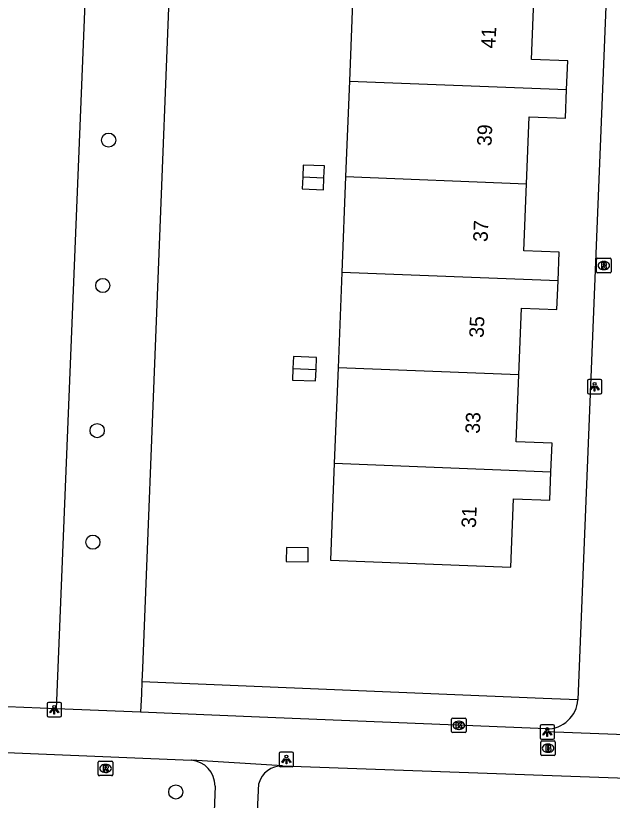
# Model space of a CAD drawing. Extents: x 160787 to 161428, y 386828 to 387483.
# Drawn here: x 161138.7 to 161179.8, y 387067.7 to 387121.8 of the extents above; entities that cross this region are included whole.
import ezdxf

# ---------------------------------------------------------------- set-up
doc = ezdxf.new("R2010")
doc.units = 0
for name, color, linetype in [('IMGEO_Boom', 7, 'Continuous'), ('IMGEO_Brandkraan', 7, 'Continuous'), ('IMGEO_Groenvoorziening', 7, 'Continuous'), ('IMGEO_Haag', 7, 'Continuous'), ('IMGEO_Kolk', 7, 'Continuous'), ('IMGEO_Lichtpunt', 7, 'Continuous'), ('IMGEO_Pand', 7, 'Continuous'), ('IMGEO_Pand_nummerreeks', 7, 'Continuous'), ('IMGEO_Rioolput', 7, 'Continuous'), ('IMGEO_Voetpad_open', 7, 'Continuous')]:
    doc.layers.add(name, color=color, linetype=linetype)

msp = doc.modelspace()

# ---------------------------------------------------------------- linework, layer by layer
at = {"layer": 'IMGEO_Boom'}
for centre in [(161145.069, 387113.242), (161144.667, 387103.214), (161144.278, 387093.199), (161143.985, 387085.507), (161149.703, 387068.275)]:
    msp.add_circle(centre, 0.489, dxfattribs=at)
at = {"layer": 'IMGEO_Brandkraan'}
for p, q in [((161174.885, 387070.866), (161174.885, 387071.718)), ((161174.96, 387071.792), (161175.812, 387071.792)), ((161175.373, 387071.572), (161175.398, 387071.572)), ((161175.886, 387071.718), (161175.886, 387070.866)), ((161175.396, 387071.012), (161175.371, 387071.012)), ((161175.812, 387070.792), (161174.96, 387070.792))]:
    msp.add_line(p, q, dxfattribs=at)
for points in [[(161174.885, 387070.866), (161174.885, 387071.718)], [(161174.96, 387071.792), (161175.812, 387071.792)], [(161175.233, 387071.492), (161175.233, 387071.092), (161175.446, 387071.092)], [(161175.464, 387071.492), (161175.233, 387071.492)], [(161175.886, 387071.718), (161175.886, 387070.866)], [(161175.412, 387071.411), (161175.358, 387071.411), (161175.358, 387071.335)], [(161175.358, 387071.335), (161175.411, 387071.335)], [(161175.42, 387071.259), (161175.358, 387071.259), (161175.358, 387071.178)], [(161175.358, 387071.178), (161175.42, 387071.178)], [(161175.812, 387070.792), (161174.96, 387070.792)]]:
    msp.add_lwpolyline(points, dxfattribs=at)
for centre, radius, start, end in [((161174.962, 387071.716), 0.0765, 91.552, 178.448), ((161174.962, 387071.716), 0.0765, 91.552, 178.448), ((161175.468, 387071.347), 0.145, 59.4692, 91.5367), ((161175.493, 387071.394), 0.0922, 285.5137, 58.1501), ((161175.81, 387071.716), 0.0765, 1.552, 88.448), ((161175.81, 387071.716), 0.0765, 1.552, 88.448), ((161175.413, 387071.373), 0.0379, 267.8285, 90.9355), ((161175.421, 387071.218), 0.0404, 269.8759, 90.5077), ((161175.452, 387071.343), 0.251, 268.6676, 293.5347), ((161175.498, 387071.202), 0.105, 301.3115, 78.989), ((161174.962, 387070.868), 0.0765, 181.552, 268.448), ((161174.962, 387070.868), 0.0765, 181.552, 268.448), ((161175.81, 387070.868), 0.0765, 271.552, 358.448), ((161175.81, 387070.868), 0.0765, 271.552, 358.448)]:
    msp.add_arc(centre, radius, start, end, dxfattribs=at)
for centre, major_axis, ratio, start_param, end_param in [((161175.372, 387071.292), (-0.387, 0.002), 0.722429, 4.712389, 7.853982), ((161175.397, 387071.292), (-0.39, 0.002), 0.717154, 1.570796, 4.712389)]:
    msp.add_ellipse(centre, major_axis=major_axis, ratio=ratio, start_param=start_param, end_param=end_param, dxfattribs=at)
at = {"layer": 'IMGEO_Groenvoorziening'}
for points in [[(161141.468, 387074.009), (161145.662, 387177.089), (161145.68, 387177.521)], [(161151.352, 387177.28), (161147.399, 387076.814), (161147.362, 387075.865)]]:
    msp.add_lwpolyline(points, dxfattribs=at)
at = {"layer": 'IMGEO_Haag'}
for points in [[(161147.362, 387075.865), (161147.329, 387075.034), (161147.279, 387073.767)], [(161177.45, 387074.628), (161175.052, 387074.729), (161147.362, 387075.865)]]:
    msp.add_lwpolyline(points, dxfattribs=at)
at = {"layer": 'IMGEO_Kolk'}
for p, q in [((161168.735, 387072.439), (161168.735, 387073.291)), ((161168.81, 387073.365), (161169.662, 387073.365)), ((161169.223, 387073.145), (161169.248, 387073.145)), ((161169.736, 387073.291), (161169.736, 387072.439)), ((161169.246, 387072.585), (161169.221, 387072.585)), ((161169.662, 387072.365), (161168.81, 387072.365))]:
    msp.add_line(p, q, dxfattribs=at)
for points in [[(161168.735, 387072.439), (161168.735, 387073.291)], [(161168.81, 387073.365), (161169.662, 387073.365)], [(161169.736, 387073.291), (161169.736, 387072.439)], [(161169.056, 387073.065), (161169.179, 387073.065), (161169.179, 387072.914), (161169.309, 387073.065), (161169.473, 387073.065), (161169.327, 387072.914), (161169.48, 387072.665), (161169.328, 387072.665), (161169.243, 387072.829), (161169.179, 387072.762), (161169.179, 387072.665), (161169.056, 387072.665), (161169.056, 387073.065)], [(161169.662, 387072.365), (161168.81, 387072.365)]]:
    msp.add_lwpolyline(points, dxfattribs=at)
for centre, start, end in [((161168.812, 387073.289), 91.552, 178.448), ((161168.812, 387073.289), 91.552, 178.448), ((161169.66, 387073.289), 1.552, 88.448), ((161169.66, 387073.289), 1.552, 88.448), ((161168.812, 387072.441), 181.552, 268.448), ((161168.812, 387072.441), 181.552, 268.448), ((161169.66, 387072.441), 271.552, 358.448), ((161169.66, 387072.441), 271.552, 358.448)]:
    msp.add_arc(centre, 0.0765, start, end, dxfattribs=at)
for centre, major_axis, ratio, start_param, end_param in [((161169.222, 387072.865), (-0.387, 0.002), 0.722429, 4.712389, 7.853982), ((161169.247, 387072.865), (-0.39, 0.002), 0.717154, 1.570796, 4.712389)]:
    msp.add_ellipse(centre, major_axis=major_axis, ratio=ratio, start_param=start_param, end_param=end_param, dxfattribs=at)
at = {"layer": 'IMGEO_Lichtpunt'}
for p, q in [((161178.1, 387096.63), (161178.1, 387095.823)), ((161178.1, 387096.63), (161178.1, 387095.823)), ((161179.002, 387096.725), (161178.194, 387096.725)), ((161179.002, 387096.725), (161178.194, 387096.725)), ((161179.096, 387095.823), (161179.096, 387096.63)), ((161179.096, 387095.823), (161179.096, 387096.63)), ((161178.194, 387095.729), (161179.002, 387095.729)), ((161178.194, 387095.729), (161179.002, 387095.729)), ((161140.823, 387074.347), (161140.823, 387073.54)), ((161140.823, 387074.347), (161140.823, 387073.54)), ((161141.725, 387074.442), (161140.917, 387074.442)), ((161141.725, 387074.442), (161140.917, 387074.442)), ((161141.819, 387073.54), (161141.819, 387074.347)), ((161141.819, 387073.54), (161141.819, 387074.347)), ((161140.917, 387073.446), (161141.725, 387073.446)), ((161140.917, 387073.446), (161141.725, 387073.446)), ((161174.833, 387072.812), (161174.833, 387072.005)), ((161174.833, 387072.812), (161174.833, 387072.005)), ((161175.735, 387072.907), (161174.927, 387072.907)), ((161175.735, 387072.907), (161174.927, 387072.907)), ((161175.829, 387072.005), (161175.829, 387072.812)), ((161175.829, 387072.005), (161175.829, 387072.812)), ((161174.927, 387071.911), (161175.735, 387071.911)), ((161174.927, 387071.911), (161175.735, 387071.911)), ((161156.838, 387070.918), (161156.838, 387070.111)), ((161156.838, 387070.918), (161156.838, 387070.111)), ((161157.74, 387071.013), (161156.932, 387071.013)), ((161157.74, 387071.013), (161156.932, 387071.013)), ((161157.834, 387070.111), (161157.834, 387070.918)), ((161157.834, 387070.111), (161157.834, 387070.918)), ((161156.932, 387070.017), (161157.74, 387070.017)), ((161156.932, 387070.017), (161157.74, 387070.017))]:
    msp.add_line(p, q, dxfattribs=at)
for points in [[(161178.474, 387096.294), (161178.513, 387096.266), (161178.325, 387096.004), (161178.287, 387096.031), (161178.474, 387096.294)], [(161178.576, 387096.246), (161178.623, 387096.246), (161178.623, 387095.924), (161178.576, 387095.924), (161178.576, 387096.246)], [(161178.686, 387096.266), (161178.724, 387096.293), (161178.911, 387096.031), (161178.872, 387096.003), (161178.686, 387096.266)], [(161141.197, 387074.011), (161141.236, 387073.983), (161141.048, 387073.721), (161141.01, 387073.748), (161141.197, 387074.011)], [(161141.299, 387073.963), (161141.346, 387073.963), (161141.346, 387073.641), (161141.299, 387073.641), (161141.299, 387073.963)], [(161141.409, 387073.983), (161141.447, 387074.01), (161141.634, 387073.748), (161141.595, 387073.72), (161141.409, 387073.983)], [(161175.207, 387072.476), (161175.246, 387072.448), (161175.058, 387072.186), (161175.02, 387072.213), (161175.207, 387072.476)], [(161175.309, 387072.428), (161175.356, 387072.428), (161175.356, 387072.106), (161175.309, 387072.106), (161175.309, 387072.428)], [(161175.419, 387072.448), (161175.457, 387072.475), (161175.644, 387072.213), (161175.605, 387072.185), (161175.419, 387072.448)], [(161157.212, 387070.582), (161157.251, 387070.554), (161157.063, 387070.292), (161157.025, 387070.319), (161157.212, 387070.582)], [(161157.314, 387070.534), (161157.361, 387070.534), (161157.361, 387070.212), (161157.314, 387070.212), (161157.314, 387070.534)], [(161157.424, 387070.554), (161157.462, 387070.581), (161157.649, 387070.319), (161157.61, 387070.291), (161157.424, 387070.554)]]:
    msp.add_lwpolyline(points, dxfattribs=at)
for centre in [(161178.599, 387096.428), (161141.322, 387074.145), (161175.332, 387072.61), (161157.337, 387070.716)]:
    msp.add_circle(centre, 0.0994, dxfattribs=at)
for centre, start, end in [((161178.194, 387096.63), 90, 180), ((161178.194, 387096.63), 90, 180), ((161179.002, 387096.63), 0, 90), ((161179.002, 387096.63), 0, 90), ((161178.194, 387095.823), 180, 270), ((161178.194, 387095.823), 180, 270), ((161179.002, 387095.823), 270, 0), ((161179.002, 387095.823), 270, 360), ((161140.917, 387074.347), 90, 180), ((161140.917, 387074.347), 90, 180), ((161141.725, 387074.347), 0, 90), ((161141.725, 387074.347), 0, 90), ((161140.917, 387073.54), 180, 270), ((161140.917, 387073.54), 180, 270), ((161141.725, 387073.54), 270, 0), ((161141.725, 387073.54), 270, 360), ((161174.927, 387072.812), 90, 180), ((161174.927, 387072.812), 90, 180), ((161175.735, 387072.812), 0, 90), ((161175.735, 387072.812), 0, 90), ((161174.927, 387072.005), 180, 270), ((161174.927, 387072.005), 180, 270), ((161175.735, 387072.005), 270, 0), ((161175.735, 387072.005), 270, 360), ((161156.932, 387070.918), 90, 180), ((161156.932, 387070.918), 90, 180), ((161157.74, 387070.918), 0, 90), ((161157.74, 387070.918), 0, 90), ((161156.932, 387070.111), 180, 270), ((161156.932, 387070.111), 180, 270), ((161157.74, 387070.111), 270, 0), ((161157.74, 387070.111), 270, 360)]:
    msp.add_arc(centre, 0.0946, start, end, dxfattribs=at)
at = {"layer": 'IMGEO_Pand'}
for points in [[(161161.945, 387123.979), (161161.681, 387117.318)], [(161176.667, 387116.725), (161176.745, 387118.702), (161174.236, 387118.802), (161174.421, 387123.485)], [(161161.681, 387117.318), (161161.42, 387110.722)], [(161161.681, 387117.318), (161176.667, 387116.725)], [(161173.899, 387110.228), (161174.082, 387114.848), (161176.589, 387114.749), (161176.667, 387116.725)], [(161159.926, 387110.645), (161159.958, 387111.459), (161158.49, 387111.517), (161158.458, 387110.703)], [(161158.458, 387110.703), (161158.425, 387109.88), (161159.893, 387109.822), (161159.926, 387110.645)], [(161158.458, 387110.703), (161159.926, 387110.645)], [(161161.42, 387110.722), (161161.159, 387104.12)], [(161161.42, 387110.722), (161173.899, 387110.228)], [(161176.075, 387103.53), (161176.154, 387105.51), (161173.716, 387105.606), (161173.899, 387110.228)], [(161161.159, 387104.12), (161160.898, 387097.533)], [(161176.075, 387103.53), (161161.159, 387104.12)], [(161173.368, 387097.04), (161173.55, 387101.648), (161175.997, 387101.551), (161176.075, 387103.53)], [(161159.377, 387097.423), (161159.409, 387098.248), (161157.822, 387098.311), (161157.789, 387097.486)], [(161157.789, 387097.486), (161157.758, 387096.691), (161159.345, 387096.628), (161159.377, 387097.423)], [(161157.789, 387097.486), (161159.377, 387097.423)], [(161160.898, 387097.533), (161160.638, 387090.954)], [(161173.368, 387097.04), (161160.898, 387097.533)], [(161175.589, 387090.362), (161175.667, 387092.33), (161173.185, 387092.428), (161173.368, 387097.04)], [(161160.638, 387090.954), (161160.373, 387084.267), (161172.819, 387083.775), (161173.005, 387088.493), (161175.511, 387088.394), (161175.589, 387090.362)], [(161160.638, 387090.954), (161175.589, 387090.362)], [(161157.325, 387084.17), (161158.826, 387084.144), (161158.843, 387085.107), (161157.342, 387085.133), (161157.325, 387084.17)]]:
    msp.add_lwpolyline(points, dxfattribs=at)
at = {"layer": 'IMGEO_Rioolput'}
for p, q in [((161178.733, 387104.162), (161178.733, 387105.014)), ((161178.808, 387105.088), (161179.66, 387105.088)), ((161179.734, 387105.014), (161179.734, 387104.162)), ((161179.221, 387104.868), (161179.246, 387104.868)), ((161179.66, 387104.088), (161178.808, 387104.088)), ((161179.244, 387104.308), (161179.219, 387104.308)), ((161144.434, 387070.396), (161145.286, 387070.396)), ((161144.359, 387069.47), (161144.359, 387070.322)), ((161144.847, 387070.176), (161144.872, 387070.176)), ((161145.36, 387070.322), (161145.36, 387069.47)), ((161145.286, 387069.396), (161144.434, 387069.396)), ((161144.87, 387069.616), (161144.845, 387069.616))]:
    msp.add_line(p, q, dxfattribs=at)
for points in [[(161178.733, 387104.162), (161178.733, 387105.014)], [(161178.808, 387105.088), (161179.66, 387105.088)], [(161179.734, 387105.014), (161179.734, 387104.162)], [(161179.322, 387104.786), (161179.07, 387104.788), (161179.07, 387104.388)], [(161179.07, 387104.388), (161179.194, 387104.388), (161179.194, 387104.55), (161179.205, 387104.55)], [(161179.248, 387104.707), (161179.194, 387104.707), (161179.194, 387104.626)], [(161179.194, 387104.626), (161179.246, 387104.626)], [(161179.252, 387104.521), (161179.323, 387104.388), (161179.463, 387104.388), (161179.398, 387104.514)], [(161179.66, 387104.088), (161178.808, 387104.088)], [(161144.434, 387070.396), (161145.286, 387070.396)], [(161144.359, 387069.47), (161144.359, 387070.322)], [(161144.948, 387070.094), (161144.696, 387070.096), (161144.696, 387069.696)], [(161144.696, 387069.696), (161144.82, 387069.696), (161144.82, 387069.858), (161144.831, 387069.858)], [(161144.874, 387070.015), (161144.82, 387070.015), (161144.82, 387069.934)], [(161144.82, 387069.934), (161144.872, 387069.934)], [(161144.878, 387069.829), (161144.949, 387069.696), (161145.089, 387069.696), (161145.024, 387069.822)], [(161145.36, 387070.322), (161145.36, 387069.47)], [(161145.286, 387069.396), (161144.434, 387069.396)]]:
    msp.add_lwpolyline(points, dxfattribs=at)
for centre, radius, start, end in [((161178.81, 387105.012), 0.0765, 91.552, 178.448), ((161178.81, 387105.012), 0.0765, 91.552, 178.448), ((161179.658, 387105.012), 0.0765, 1.552, 88.448), ((161179.658, 387105.012), 0.0765, 1.552, 88.448), ((161179.204, 387104.497), 0.0533, 26.0293, 88.6989), ((161179.23, 387104.815), 0.19, 274.7715, 282.9687), ((161179.254, 387104.611), 0.0964, 77.0061, 93.1865), ((161179.268, 387104.668), 0.0378, 276.6634, 79.6772), ((161179.321, 387104.676), 0.109, 350.3612, 89.416), ((161179.319, 387104.676), 0.112, 277.5842, 350.9817), ((161179.303, 387104.461), 0.108, 29.5134, 73.7905), ((161178.81, 387104.164), 0.0765, 181.552, 268.448), ((161178.81, 387104.164), 0.0765, 181.552, 268.448), ((161179.658, 387104.164), 0.0765, 271.552, 358.448), ((161179.658, 387104.164), 0.0765, 271.552, 358.448), ((161144.436, 387070.32), 0.0765, 91.552, 178.448), ((161144.436, 387070.32), 0.0765, 91.552, 178.448), ((161145.284, 387070.32), 0.0765, 1.552, 88.448), ((161145.284, 387070.32), 0.0765, 1.552, 88.448), ((161144.83, 387069.805), 0.0533, 26.0293, 88.6989), ((161144.856, 387070.123), 0.19, 274.7715, 282.9687), ((161144.88, 387069.919), 0.0964, 77.0061, 93.1865), ((161144.894, 387069.976), 0.0378, 276.6634, 79.6772), ((161144.947, 387069.984), 0.109, 350.3612, 89.416), ((161144.945, 387069.984), 0.112, 277.5842, 350.9817), ((161144.929, 387069.769), 0.108, 29.5134, 73.7905), ((161144.436, 387069.472), 0.0765, 181.552, 268.448), ((161144.436, 387069.472), 0.0765, 181.552, 268.448), ((161145.284, 387069.472), 0.0765, 271.552, 358.448), ((161145.284, 387069.472), 0.0765, 271.552, 358.448)]:
    msp.add_arc(centre, radius, start, end, dxfattribs=at)
for centre, major_axis, ratio, start_param, end_param in [((161179.22, 387104.588), (-0.387, 0.002), 0.722429, 4.712389, 7.853982), ((161179.245, 387104.588), (-0.39, 0.002), 0.717154, 1.570796, 4.712389), ((161144.846, 387069.896), (-0.387, 0.002), 0.722429, 4.712389, 7.853982), ((161144.871, 387069.896), (-0.39, 0.002), 0.717154, 1.570796, 4.712389)]:
    msp.add_ellipse(centre, major_axis=major_axis, ratio=ratio, start_param=start_param, end_param=end_param, dxfattribs=at)
at = {"layer": 'IMGEO_Voetpad_open'}
for points in [[(161181.538, 387176.158), (161179.445, 387124.181), (161177.818, 387083.794), (161177.45, 387074.628)], [(161141.468, 387074.009), (161129.056, 387074.52)], [(161147.279, 387073.767), (161141.468, 387074.009)], [(161175.269, 387072.619), (161155.473, 387073.431), (161147.279, 387073.767)], [(161181.932, 387072.363), (161181.924, 387072.163), (161175.261, 387072.419), (161175.269, 387072.619)], [(161128.864, 387071.378), (161129.133, 387071.365), (161150.759, 387070.455)], [(161157.068, 387070.064), (161150.793, 387070.458), (161150.759, 387070.455)], [(161157.068, 387070.064), (161184.654, 387069.093)], [(161155.234, 387064.503), (161155.427, 387068.849)], [(161152.41, 387068.67), (161149.703, 387000), (161148.087, 386963.017)]]:
    msp.add_lwpolyline(points, dxfattribs=at)
for centre, radius, start, end in [((161175.282, 387074.793), 2.174, 269.6605, 355.6381), ((161150.652, 387068.7), 1.758, 359.0199, 86.5134), ((161157.02, 387068.413), 1.652, 88.3506, 164.682)]:
    msp.add_arc(centre, radius, start, end, dxfattribs=at)

# ---------------------------------------------------------------- texts
at = {"layer": 'IMGEO_Pand_nummerreeks'}
for s, p in [('41', (161171.756, 387119.547)), ('39', (161171.482, 387112.819)), ('37', (161171.212, 387106.204)), ('35', (161170.942, 387099.59)), ('33', (161170.672, 387092.975)), ('31', (161170.406, 387086.473))]:
    msp.add_text(s, height=1, rotation=87.6639, dxfattribs=at).set_placement(p)

doc.saveas('drawing.dxf')
